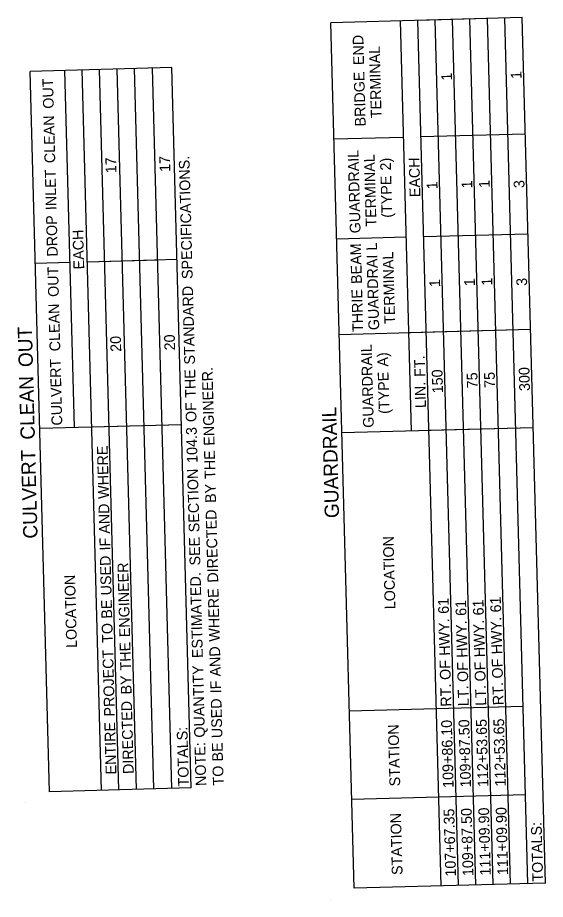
# Model space of a CAD drawing. Extents: x 1930078 to 1931323, y 596452 to 607874.
# Drawn here: x 1930935.6 to 1931231.4, y 599182.3 to 599676.8 of the extents above; entities that cross this region are included whole.
import ezdxf

# ---------------------------------------------------------------- set-up
doc = ezdxf.new("R2010")
doc.units = 0
doc.layers.add('Default', color=7, linetype='Continuous')
doc.layers.add('R_Border', color=7, linetype='Continuous')

msp = doc.modelspace()

# ---------------------------------------------------------------- linework, layer by layer
at = {"layer": 'Default'}
for p, q in [((1931218.38, 599676.81), (1931111.17, 599673.93)), ((1931198.89, 599676.28), (1931159.9, 599675.24)), ((1931172.93, 599189.86), (1931159.9, 599675.24)), ((1931182.68, 599190.12), (1931169.65, 599675.5)), ((1931192.43, 599190.39), (1931179.4, 599675.76)), ((1931202.17, 599190.65), (1931189.14, 599676.02)), ((1931211.92, 599190.91), (1931198.89, 599676.28)), ((1931221.67, 599191.17), (1931208.64, 599676.55)), ((1931231.41, 599191.43), (1931218.38, 599676.81)), ((1931124.2, 599188.55), (1931111.17, 599673.93)), ((1931156.33, 599444.96), (1931150.16, 599674.98)), ((1931021.99, 599648.8), (1930942.55, 599646.66)), ((1931021.99, 599648.8), (1930942.55, 599646.66)), ((1930953.4, 599242.67), (1930942.55, 599646.66)), ((1930967.42, 599446.9), (1930962.05, 599647.19)), ((1930982.64, 599243.46), (1930971.79, 599647.45)), ((1930992.38, 599243.72), (1930981.54, 599647.71)), ((1931002.13, 599243.98), (1930991.29, 599647.97)), ((1931011.88, 599244.24), (1931001.03, 599648.23)), ((1931022.11, 599244.52), (1931011.27, 599648.51)), ((1931022.11, 599244.52), (1931011.27, 599648.51)), ((1931032.83, 599244.8), (1931021.99, 599648.8)), ((1931220.14, 599611.51), (1931161.66, 599609.94)), ((1931220.14, 599611.51), (1931161.66, 599609.94)), ((1931151.91, 599609.67), (1931112.92, 599608.63)), ((1931153.41, 599553.63), (1931114.43, 599552.59)), ((1931221.64, 599555.46), (1931163.16, 599553.89)), ((1931221.64, 599555.46), (1931163.16, 599553.89)), ((1930964.94, 599539.49), (1930945.44, 599538.97)), ((1931024.88, 599541.1), (1930974.68, 599539.75)), ((1931014.16, 599540.81), (1930974.68, 599539.75)), ((1931223.08, 599501.86), (1931115.87, 599498.98)), ((1931223.08, 599501.86), (1931154.85, 599500.03)), ((1931027.36, 599448.51), (1930947.93, 599446.37)), ((1931027.36, 599448.51), (1930977.17, 599447.16)), ((1931224.56, 599446.79), (1931117.35, 599443.91)), ((1931224.56, 599446.79), (1931166.08, 599445.22)), ((1931219, 599290.58), (1931121.53, 599287.97)), ((1931219, 599290.58), (1931170.26, 599289.28)), ((1931032.83, 599244.8), (1930953.4, 599242.67)), ((1931032.83, 599244.8), (1930953.4, 599242.67)), ((1931220.33, 599240.88), (1931122.87, 599238.26)), ((1931220.33, 599240.88), (1931171.6, 599239.57)), ((1931231.41, 599191.43), (1931124.2, 599188.55)), ((1931231.41, 599191.43), (1931124.2, 599188.55))]:
    msp.add_line(p, q, dxfattribs=at)
at = {"layer": 'R_Border'}
for p, q in [((1930939.91, 599236.46), (1930939.91, 599236.46)), ((1931110.71, 599182.34), (1931110.71, 599182.34))]:
    msp.add_line(p, q, dxfattribs=at)

# ---------------------------------------------------------------- texts
at = {"layer": 'Default'}
for s, height, p in [(' END', 6, (1931129.87, 599648.05)), ('TERMINAL', 6, (1931139.62, 599620.48)), ('BRIDGE', 6, (1931130.74, 599615.87)), ('1', 6, (1931179.12, 599641.52)), ('1', 6, (1931218.1, 599642.47)), (' OUT', 6, (1930955.93, 599623.59)), (' CLEAN', 6, (1930956.75, 599593.07)), ('GUARDRAIL', 6, (1931127.84, 599555.95)), ('17', 6, (1930990.98, 599589.6)), ('17', 6, (1931021.19, 599590.41)), (' SPECIFICATIONS.', 6, (1931033.78, 599528.07)), ('TERMINAL', 6, (1931136.75, 599559.69)), (' 2)', 6, (1931144.96, 599588.92)), ('EACH', 6, (1931161.36, 599576.18)), (' INLET', 6, (1930957.45, 599566.71)), ('(TYPE', 6, (1931145.62, 599564.65)), ('1', 6, (1931171, 599580.59)), ('1', 6, (1931190.49, 599581.11)), ('1', 6, (1931200.24, 599581.37)), ('3', 6, (1931219.75, 599581.3)), ('DROP', 6, (1930958.09, 599542.87)), ('EACH', 6, (1930972.92, 599535.7)), (' BEAM', 6, (1931128.67, 599525.31)), ('L', 6, (1931137.11, 599546.26)), ('GUARDRAI', 6, (1931138.3, 599501.64)), ('TERMINAL', 6, (1931147.21, 599505.11)), (' OUT', 6, (1930958.76, 599518.05)), ('1', 6, (1931172.47, 599525.76)), ('1', 6, (1931191.96, 599526.28)), ('1', 6, (1931201.71, 599526.55)), ('3', 6, (1931221.22, 599526.48)), (' STANDARD', 6, (1931035.07, 599480.09)), ('THRIE', 6, (1931129.33, 599500.58)), (' CLEAN', 6, (1930959.58, 599487.53)), (' OUT', 8, (1930944.26, 599477.98)), ('20', 6, (1930993.66, 599489.47)), ('20', 6, (1931023.88, 599490.29)), ('GUARDRAIL', 6, (1931135.27, 599446.91)), (' A)', 6, (1931143.42, 599478.94)), ('CULVERT', 6, (1930960.64, 599448.12)), (' FT.', 6, (1931164.13, 599473.19)), (' THE', 6, (1931035.57, 599461.45)), (' ENGINEER.', 6, (1931046.04, 599434.61)), ('(TYPE', 6, (1931144.07, 599454.67)), ('150', 6, (1931174.07, 599466.2)), ('75', 6, (1931193.5, 599469.02)), ('75', 6, (1931203.25, 599469.28)), ('300', 6, (1931222.8, 599467.51)), (' CLEAN', 8, (1930945.35, 599437.28)), ('LIN.', 6, (1931164.54, 599457.94)), (' OF', 6, (1931035.93, 599447.86)), ('GUARDRAIL', 8, (1931115.8, 599396.26)), (' 104.3', 6, (1931036.55, 599424.96)), ('CULVERT', 8, (1930946.76, 599384.74)), (' WHERE', 6, (1930986.86, 599404.8)), (' THE', 6, (1931046.54, 599415.97)), (' SECTION', 6, (1931037.59, 599386.06)), (' BY', 6, (1931046.9, 599402.52)), (' AND', 6, (1930987.38, 599385.23)), (' DIRECTED', 6, (1931048.11, 599357.8)), (' IF', 6, (1930987.64, 599375.84)), (' SEE', 6, (1931038.09, 599367.41)), ('LOCATION', 6, (1931147.38, 599345.13)), (' USED', 6, (1930988.31, 599350.67)), (' ENGINEER', 6, (1930998.7, 599327.2)), ('LOCATION', 6, (1930968.86, 599323.45)), (' ESTIMATED.', 6, (1931039.49, 599315.52)), (' WHERE', 6, (1931048.99, 599324.73)), (' BE', 6, (1930988.66, 599337.61)), (' 61', 6, (1931177.45, 599340.31)), (' 61', 6, (1931187.23, 599339.17)), (' 61', 6, (1931196.98, 599339.43)), (' 61', 6, (1931206.69, 599341.09)), (' HWY.', 6, (1931178.08, 599316.83)), (' HWY.', 6, (1931207.32, 599317.62)), (' TO', 6, (1930989.03, 599324.02)), (' HWY.', 6, (1931187.86, 599315.7)), (' HWY.', 6, (1931197.61, 599315.96)), (' THE', 6, (1930999.2, 599308.56)), (' PROJECT', 6, (1930990.14, 599282.74)), (' AND', 6, (1931049.52, 599305.15)), (' OF', 6, (1931178.44, 599303.25)), (' OF', 6, (1931188.23, 599302.12)), (' OF', 6, (1931197.97, 599302.38)), (' OF', 6, (1931207.68, 599304.03)), (' QUANTITY', 6, (1931040.68, 599270.89)), (' BY', 6, (1930999.56, 599295.11)), (' IF', 6, (1931049.77, 599295.76)), ('RT.', 6, (1931178.79, 599290.48)), ('LT.', 6, (1931188.53, 599290.74)), ('LT.', 6, (1931198.28, 599291)), ('RT.', 6, (1931208.02, 599291.27)), (' USED', 6, (1931050.45, 599270.6)), ('DIRECTED', 6, (1931000.7, 599252.72)), ('ENTIRE', 6, (1930990.95, 599252.46)), ('STATION', 6, (1931150.05, 599245.79)), ('109+86.10', 6, (1931180.01, 599244.94)), ('109+87.50', 6, (1931189.75, 599245.2)), ('112+53.65', 6, (1931199.5, 599245.43)), ('112+53.65', 6, (1931209.25, 599245.69)), ('TOTALS:', 6, (1931031.61, 599245.75)), ('NOTE:', 6, (1931041.35, 599246.01)), (' BE', 6, (1931050.8, 599257.53)), ('TO', 6, (1931051.1, 599246.27)), ('STATION', 6, (1931151.38, 599196.09)), ('107+67.35', 6, (1931181.34, 599195.2)), ('109+87.50', 6, (1931191.09, 599195.49)), ('111+09.90', 6, (1931200.83, 599195.76)), ('111+09.90', 6, (1931210.58, 599196.02)), ('TOTALS:', 6, (1931230.19, 599192.37))]:
    msp.add_text(s, height=height, rotation=91.5377, dxfattribs=at).set_placement(p)

doc.saveas('drawing.dxf')
